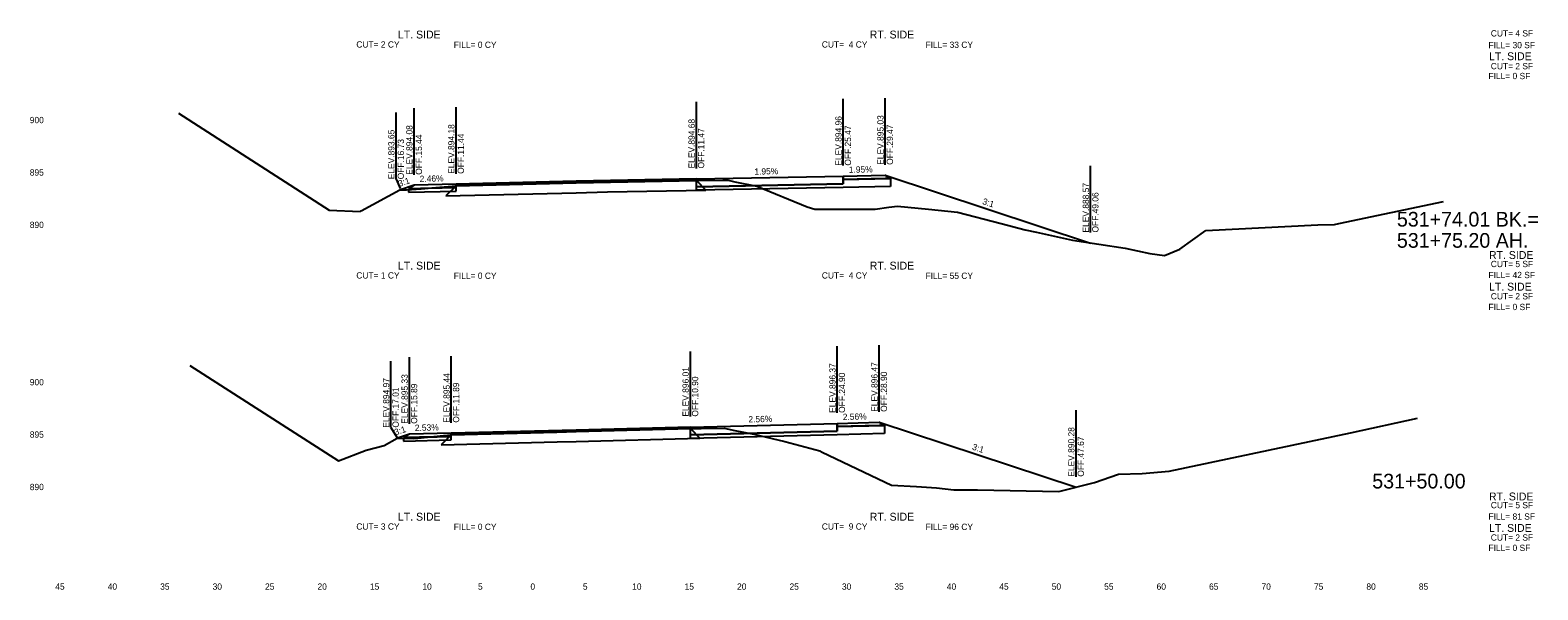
# Model space of a CAD drawing. Extents: x -4 to 359, y 0 to 1436.
# Drawn here: x -3.9 to 139.8, y 450.5 to 503.9 of the extents above; entities that cross this region are included whole.
import ezdxf

# ---------------------------------------------------------------- set-up
doc = ezdxf.new("R2010")
doc.units = 0
for name, color, linetype in [('XS-Existing subsurface-pavement', 7, 'Continuous'), ('XS-Existing surface-ground', 7, 'Continuous'), ('XS-Proposed Finish Grade', 7, 'Continuous'), ('XS-Proposed subsurface-aggregate layer 1', 7, 'Continuous'), ('XS-Proposed surface-ground', 7, 'Continuous'), ('XS-Proposed surface-pavement', 7, 'Continuous'), ('XS-Proposed surface-shoulder', 7, 'Continuous'), ('XS-Text-ditch slope', 7, 'Continuous'), ('XS-Text-earthwork labels', 7, 'Continuous'), ('XS-Text-elevation', 7, 'Continuous'), ('XS-Text-offset label', 7, 'Continuous'), ('XS-Text-pavement elevation', 7, 'Continuous'), ('XS-Text-pavement slope', 7, 'Continuous'), ('XS-Text-profile report', 7, 'Continuous'), ('XS-Text-shoulder elevation', 7, 'Continuous'), ('XS-Text-shoulder slope', 7, 'Continuous'), ('XS-Text-tie elevation', 7, 'Continuous'), ('XS-Text-tie offset', 7, 'Continuous')]:
    doc.layers.add(name, color=color, linetype=linetype)

msp = doc.modelspace()

# ---------------------------------------------------------------- linework, layer by layer
at = {"layer": 'XS-Existing subsurface-pavement'}
for p, q in [((36.69, 489.02), (35.73, 488.06)), ((59.6, 489.52), (60.52, 488.6)), ((35.73, 488.06), (48.15, 488.36)), ((48.15, 488.36), (51.14, 488.44)), ((51.13, 488.44), (60.52, 488.6)), ((59.03, 465.86), (59.94, 464.94)), ((36.24, 465.28), (35.27, 464.31)), ((35.27, 464.31), (46.32, 464.59)), ((46.32, 464.59), (48.15, 464.64)), ((48.15, 464.64), (59.94, 464.94))]:
    msp.add_line(p, q, dxfattribs=at)
at = {"layer": 'XS-Existing surface-ground'}
for p, q in [((10.24, 495.93), (24.58, 486.69)), ((33.37, 488.72), (34.39, 488.82)), ((34.39, 488.82), (36.69, 489.02)), ((36.69, 489.02), (48.13, 489.3)), ((48.13, 489.3), (51.11, 489.37)), ((51.11, 489.37), (59.6, 489.52)), ((59.6, 489.52), (62.12, 489.55)), ((62.12, 489.55), (62.62, 489.54)), ((62.62, 489.54), (63.26, 489.39)), ((63.26, 489.39), (65.38, 488.98)), ((65.38, 488.98), (70.18, 487.02)), ((27.66, 486.62), (31.33, 488.64)), ((31.33, 488.64), (31.96, 488.63)), ((31.96, 488.63), (33.37, 488.72)), ((120.87, 485.42), (130.82, 487.53)), ((24.58, 486.69), (27.55, 486.56)), ((27.55, 486.56), (27.66, 486.62)), ((70.18, 487.02), (70.91, 486.79)), ((70.91, 486.79), (71.91, 486.79)), ((71.91, 486.79), (76.65, 486.8)), ((76.65, 486.8), (77.95, 486.99)), ((77.95, 486.99), (78.77, 487.08)), ((78.77, 487.08), (81.73, 486.79)), ((81.73, 486.79), (84.49, 486.51)), ((84.49, 486.51), (88.65, 485.42)), ((88.65, 485.42), (90.96, 484.83)), ((90.96, 484.83), (92.04, 484.6)), ((92.04, 484.6), (95.47, 483.82)), ((105.69, 482.98), (108.19, 484.77)), ((108.19, 484.77), (118.86, 485.31)), ((118.86, 485.31), (120.43, 485.34)), ((120.43, 485.34), (120.87, 485.42)), ((95.47, 483.82), (100.48, 483.06)), ((100.48, 483.06), (102.83, 482.56)), ((104.24, 482.38), (105.69, 482.98)), ((102.83, 482.56), (104.24, 482.38)), ((11.32, 471.88), (25.5, 462.8)), ((48.13, 465.58), (59.03, 465.86)), ((59.03, 465.86), (60.07, 465.88)), ((60.07, 465.88), (62.24, 465.9)), ((62.24, 465.9), (63.26, 465.68)), ((121.98, 465.47), (128.34, 466.84)), ((29.83, 464.26), (31.08, 464.95)), ((31.08, 464.95), (32.59, 464.93)), ((32.59, 464.93), (33.05, 464.96)), ((33.05, 464.96), (35.5, 465.21)), ((35.5, 465.21), (36.24, 465.28)), ((36.24, 465.28), (46.3, 465.53)), ((46.3, 465.53), (48.13, 465.58)), ((63.26, 465.68), (65.07, 465.33)), ((65.07, 465.33), (68.05, 464.63)), ((68.05, 464.63), (71.36, 463.73)), ((104.68, 461.79), (121.98, 465.47)), ((25.5, 462.8), (28.11, 463.8)), ((28.11, 463.8), (29.83, 464.26)), ((71.36, 463.73), (71.59, 463.6)), ((71.59, 463.6), (78.21, 460.45)), ((97.56, 460.72), (99.85, 461.51)), ((99.85, 461.51), (102.09, 461.57)), ((102.09, 461.57), (104.68, 461.79)), ((78.21, 460.45), (80.58, 460.33)), ((80.58, 460.33), (82.5, 460.21)), ((82.5, 460.21), (84.16, 460.02)), ((84.16, 460.02), (86.41, 460.01)), ((86.41, 460.01), (94.16, 459.85)), ((94.16, 459.85), (97.56, 460.72))]:
    msp.add_line(p, q, dxfattribs=at)
at = {"layer": 'XS-Proposed Finish Grade'}
for points in [[(36.69, 489.16), (32.69, 489.07)], [(36.69, 489.16), (48.13, 489.45), (59.6, 489.67)], [(59.6, 489.67), (73.6, 489.94)], [(73.6, 489.94), (77.6, 490.02)], [(36.24, 465.42), (48.13, 465.72), (59.03, 466)], [(59.03, 466), (73.03, 466.36)], [(73.03, 466.36), (77.03, 466.46)], [(36.24, 465.42), (32.24, 465.32)]]:
    msp.add_lwpolyline(points, dxfattribs=at)
at = {"layer": 'XS-Proposed subsurface-aggregate layer 1'}
for points in [[(36.69, 488.85), (32.15, 488.74)], [(32.15, 488.74), (32.15, 488.41)], [(36.69, 488.52), (36.69, 488.85)], [(59.6, 488.92), (73.6, 489.19)], [(78.1, 488.95), (73.6, 488.86), (59.6, 488.59)], [(59.6, 488.59), (59.6, 488.92)], [(73.6, 489.63), (78.1, 489.72)], [(73.6, 489.19), (73.6, 489.63)], [(78.1, 489.72), (78.1, 488.95)], [(32.15, 488.41), (36.69, 488.52)], [(73.03, 466.05), (77.53, 466.16)], [(73.03, 465.61), (73.03, 466.05)], [(77.53, 466.16), (77.53, 465.39)], [(36.24, 465.11), (31.69, 465)], [(31.69, 465), (31.69, 464.66)], [(31.69, 464.66), (36.24, 464.78)], [(36.24, 464.78), (36.24, 465.11)], [(59.03, 465.25), (73.03, 465.61)], [(77.53, 465.39), (73.03, 465.28), (59.03, 464.92)], [(59.03, 464.92), (59.03, 465.25)]]:
    msp.add_lwpolyline(points, dxfattribs=at)
at = {"layer": 'XS-Proposed surface-ground'}
for points in [[(32.69, 489.07), (31.4, 488.64)], [(77.6, 490.02), (97.19, 483.56)], [(77.03, 466.46), (95.8, 460.27)], [(32.24, 465.32), (31.12, 464.95)]]:
    msp.add_lwpolyline(points, dxfattribs=at)
at = {"layer": 'XS-Proposed surface-pavement'}
for points in [[(59.6, 489.67), (48.13, 489.45), (36.69, 489.16)], [(36.69, 489.02), (48.13, 489.3), (59.6, 489.52)], [(36.69, 489.16), (36.69, 489.02)], [(59.6, 489.67), (73.6, 489.94)], [(59.6, 488.92), (59.6, 489.67)], [(59.6, 489.52), (59.6, 489.67)], [(73.6, 489.19), (59.6, 488.92)], [(73.6, 489.94), (73.6, 489.19)], [(59.03, 466), (48.13, 465.72), (36.24, 465.42)], [(36.24, 465.28), (48.13, 465.58), (59.03, 465.86)], [(59.03, 466), (73.03, 466.36)], [(59.03, 465.25), (59.03, 466)], [(59.03, 465.86), (59.03, 466)], [(73.03, 466.36), (73.03, 465.61)], [(36.24, 465.42), (36.24, 465.28)], [(73.03, 465.61), (59.03, 465.25)]]:
    msp.add_lwpolyline(points, dxfattribs=at)
at = {"layer": 'XS-Proposed surface-shoulder'}
for points in [[(36.69, 489.16), (32.69, 489.07), (32.15, 488.74)], [(32.15, 488.74), (32.69, 488.75), (36.69, 488.85)], [(36.69, 488.85), (36.69, 489.16)], [(73.6, 489.94), (77.6, 490.02), (78.1, 489.72)], [(73.6, 489.63), (73.6, 489.94)], [(78.1, 489.72), (77.6, 489.71), (73.6, 489.63)], [(73.03, 466.36), (77.03, 466.46), (77.53, 466.16)], [(73.03, 466.05), (73.03, 466.36)], [(77.53, 466.16), (77.03, 466.15), (73.03, 466.05)], [(36.24, 465.42), (32.24, 465.32), (31.69, 465)], [(31.69, 465), (32.24, 465.01), (36.24, 465.11)], [(36.24, 465.11), (36.24, 465.42)]]:
    msp.add_lwpolyline(points, dxfattribs=at)
at = {"layer": 'XS-Text-tie offset'}
for p, q in [((77.6, 491.02), (77.6, 497.37)), ((30.97, 489.64), (30.97, 496)), ((32.69, 490.07), (32.69, 496.42)), ((36.69, 490.16), (36.69, 496.51)), ((59.6, 490.67), (59.6, 497.02)), ((73.6, 490.94), (73.6, 497.32)), ((97.19, 484.56), (97.19, 490.91)), ((30.97, 489.64), (31.35, 488.75)), ((59.03, 467), (59.03, 473.2)), ((73.03, 467.36), (73.03, 473.71)), ((77.03, 467.46), (77.03, 473.81)), ((30.48, 465.95), (30.48, 472.3)), ((32.24, 466.32), (32.24, 472.67)), ((36.24, 466.42), (36.24, 472.77)), ((95.8, 461.27), (95.8, 467.62)), ((30.48, 465.95), (31.06, 465.03))]:
    msp.add_line(p, q, dxfattribs=at)

# ---------------------------------------------------------------- texts
at = {"layer": 'XS-Text-ditch slope'}
for rotation, p in [(18.2629, (31.29, 488.92)), (341.7371, (86.82, 487.29)), (18.2629, (30.92, 465.2)), (341.7371, (85.85, 463.87))]:
    msp.add_text('3:1', height=0.6, rotation=rotation, dxfattribs=at).set_placement(p)
at = {"layer": 'XS-Text-earthwork labels'}
for s, height, p in [('LT. SIDE', 0.75, (31.15, 503.07)), ('RT. SIDE', 0.75, (76.13, 503.07)), (' CUT= 4 SF           ', 0.6, (135.12, 503.26)), (' CUT= 2 CY           ', 0.6, (26.96, 502.2)), ('FILL= 0 CY           ', 0.6, (36.47, 502.17)), (' CUT=  4 CY           ', 0.6, (71.34, 502.2)), ('FILL= 33 CY           ', 0.6, (81.45, 502.17)), ('FILL= 30 SF           ', 0.6, (135.12, 502.14)), ('LT. SIDE', 0.75, (135.17, 501)), (' CUT= 2 SF           ', 0.6, (135.12, 500.13)), ('FILL= 0 SF           ', 0.6, (135.12, 499.19)), ('LT. SIDE', 0.75, (31.15, 481.03)), ('RT. SIDE', 0.75, (76.13, 481.03)), ('RT. SIDE', 0.75, (135.17, 482.04)), (' CUT= 5 SF           ', 0.6, (135.12, 481.26)), (' CUT= 1 CY           ', 0.6, (26.96, 480.17)), ('FILL= 0 CY           ', 0.6, (36.47, 480.14)), (' CUT=  4 CY           ', 0.6, (71.34, 480.17)), ('FILL= 55 CY           ', 0.6, (81.45, 480.14)), ('FILL= 42 SF           ', 0.6, (135.12, 480.21)), ('LT. SIDE', 0.75, (135.17, 479.02)), (' CUT= 2 SF           ', 0.6, (135.12, 478.18)), ('FILL= 0 SF           ', 0.6, (135.12, 477.16)), ('RT. SIDE', 0.75, (135.17, 459.01)), (' CUT= 5 SF           ', 0.6, (135.12, 458.26)), ('LT. SIDE', 0.75, (31.15, 457.08)), ('RT. SIDE', 0.75, (76.13, 457.08)), ('FILL= 81 SF           ', 0.6, (135.12, 457.17)), (' CUT= 3 CY           ', 0.6, (26.96, 456.22)), ('FILL= 0 CY           ', 0.6, (36.47, 456.19)), (' CUT=  9 CY           ', 0.6, (71.34, 456.22)), ('FILL= 96 CY           ', 0.6, (81.45, 456.19)), ('LT. SIDE', 0.75, (135.17, 456.01)), (' CUT= 2 SF           ', 0.6, (135.12, 455.17)), ('FILL= 0 SF           ', 0.6, (135.12, 454.18))]:
    msp.add_text(s, height=height, dxfattribs=at).set_placement(p)
at = {"layer": 'XS-Text-elevation'}
for s, p in [('           900           ', (-6.4, 494.99)), ('           895           ', (-6.4, 489.99)), ('           890           ', (-6.4, 484.99)), ('           900           ', (-6.4, 469.99)), ('           895           ', (-6.4, 464.99)), ('           890           ', (-6.4, 459.99))]:
    msp.add_text(s, height=0.6, dxfattribs=at).set_placement(p)
at = {"layer": 'XS-Text-offset label'}
for s, height, p in [('531+74.01 BK.= ', 1.4, (126.39, 485.13)), ('531+75.20 AH.          ', 1.4, (126.39, 483.11)), ('           531+50.00           ', 1.4, (118.32, 460.15)), ('           45           ', 0.6, (-3.97, 450.49)), ('           40           ', 0.6, (1.03, 450.49)), ('           35           ', 0.6, (6.03, 450.49)), ('           30           ', 0.6, (11.03, 450.49)), ('           25           ', 0.6, (16.03, 450.49)), ('           20           ', 0.6, (21.03, 450.49)), ('           15           ', 0.6, (26.03, 450.49)), ('           10           ', 0.6, (31.03, 450.49)), ('           5           ', 0.6, (36.33, 450.49)), ('           0           ', 0.6, (41.33, 450.49)), ('           0           ', 0.6, (41.33, 450.49)), ('           5           ', 0.6, (46.33, 450.49)), ('           10           ', 0.6, (51.03, 450.49)), ('           15           ', 0.6, (56.03, 450.49)), ('           20           ', 0.6, (61.03, 450.49)), ('           25           ', 0.6, (66.03, 450.49)), ('           30           ', 0.6, (71.03, 450.49)), ('           35           ', 0.6, (76.03, 450.49)), ('           40           ', 0.6, (81.03, 450.49)), ('           45           ', 0.6, (86.03, 450.49)), ('           50           ', 0.6, (91.03, 450.49)), ('           55           ', 0.6, (96.03, 450.49)), ('           60           ', 0.6, (101.03, 450.49)), ('           65           ', 0.6, (106.03, 450.49)), ('           70           ', 0.6, (111.03, 450.49)), ('           75           ', 0.6, (116.03, 450.49)), ('           80           ', 0.6, (121.03, 450.49)), ('           85           ', 0.6, (126.03, 450.49))]:
    msp.add_text(s, height=height, dxfattribs=at).set_placement(p)
at = {"layer": 'XS-Text-pavement elevation'}
for s, p in [('ELEV.894.08', (32.54, 490.07)), ('ELEV.894.18', (36.54, 490.16)), ('ELEV.894.68', (59.45, 490.67)), ('ELEV.894.96', (73.45, 490.94)), ('OFF.25.47', (74.35, 490.94)), ('OFF.15.44', (33.44, 490.07)), ('OFF.11.44', (37.44, 490.16)), ('OFF.11.47', (60.35, 490.67)), ('ELEV.896.01', (58.88, 467)), ('ELEV.896.37', (72.88, 467.36)), ('ELEV.895.33', (32.09, 466.32)), ('OFF.15.89', (32.99, 466.32)), ('ELEV.895.44', (36.09, 466.42)), ('OFF.11.89', (36.99, 466.42)), ('OFF.10.90', (59.78, 467)), ('OFF.24.90', (73.78, 467.36))]:
    msp.add_text(s, height=0.6, rotation=90, dxfattribs=at).set_placement(p)
at = {"layer": 'XS-Text-pavement slope'}
for s, rotation, p in [('1.95%', 1.1189, (65.14, 490.08)), ('2.56%', 1.4638, (64.57, 466.44))]:
    msp.add_text(s, height=0.6, rotation=rotation, dxfattribs=at).set_placement(p)
at = {"layer": 'XS-Text-profile report'}
for s, p in [('Shldr_Surf_Asph_B2', (32.13, 488.74)), ('Shldr_Surf_Asph_T1', (32.68, 489.06)), ('Shldr_Surf_Asph_B1', (32.68, 488.75)), ('Pvmt_Surf_Asph_T2_L', (36.68, 489.16)), ('Pvmt_Surf_Asph_T_L', (36.68, 489.02)), ('Shldr_Surf_Asph_B12', (36.68, 488.85)), ('Pvmt_Surf_Asph_T1', (48.12, 489.44)), ('Pvmt_Surf_Asph_T', (48.12, 489.3)), ('Pvmt_Surf_Asph_T1_R', (59.58, 489.67)), ('Pvmt_Surf_Asph_T_R', (59.58, 489.52)), ('Pvmt_Surf_Conc_B_R', (59.58, 488.92)), ('Shldr_Surf_Asph_B111', (73.58, 489.63)), ('Pvmt_Surf_Conc_T1_R', (73.59, 489.94)), ('Pvmt_Surf_Conc_B1_R', (73.59, 489.19)), ('Agg_Layer_1_B11', (73.59, 488.86)), ('Shldr_Surf_Asph_T11', (77.59, 490.02)), ('Shldr_Surf_Asph_B11', (77.59, 489.71)), ('Shldr_Surf_Asph_B21', (78.09, 489.72)), ('Agg_Layer_1_B12', (78.09, 488.95)), ('Rt_Agg_Layer_1_B13', (80.69, 489)), ('Fill_Slope_2_B', (31.39, 488.64)), ('Agg_Layer_1_B1', (32.14, 488.41)), ('Agg_Layer_1_B', (36.68, 488.52)), ('Agg_Layer_1_B2', (59.58, 488.59)), ('Fill_Slope_2_B1', (97.18, 483.56)), ('Pvmt_Surf_Asph_T1', (48.12, 465.72)), ('Pvmt_Surf_Asph_T1_R', (59.01, 466)), ('Pvmt_Surf_Asph_T_R', (59.01, 465.85)), ('Pvmt_Surf_Conc_T1_R', (73.02, 466.36)), ('Shldr_Surf_Asph_B111', (73.02, 466.05)), ('Shldr_Surf_Asph_T11', (77.02, 466.46)), ('Shldr_Surf_Asph_B11', (77.02, 466.15)), ('Shldr_Surf_Asph_B21', (77.52, 466.16)), ('Fill_Slope_2_B', (31.11, 464.95)), ('Shldr_Surf_Asph_B2', (31.68, 464.99)), ('Agg_Layer_1_B1', (31.68, 464.66)), ('Shldr_Surf_Asph_T1', (32.22, 465.32)), ('Shldr_Surf_Asph_B1', (32.22, 465.01)), ('Pvmt_Surf_Asph_T2_L', (36.22, 465.42)), ('Pvmt_Surf_Asph_T_L', (36.22, 465.28)), ('Shldr_Surf_Asph_B12', (36.22, 465.11)), ('Agg_Layer_1_B', (36.23, 464.78)), ('Pvmt_Surf_Asph_T', (48.12, 465.58)), ('Pvmt_Surf_Conc_B_R', (59.01, 465.25)), ('Agg_Layer_1_B2', (59.02, 464.92)), ('Pvmt_Surf_Conc_B1_R', (73.02, 465.61)), ('Agg_Layer_1_B11', (73.02, 465.28)), ('Agg_Layer_1_B12', (77.52, 465.39)), ('Rt_Agg_Layer_1_B13', (80.06, 465.46)), ('Fill_Slope_2_B1', (95.79, 460.27))]:
    msp.add_text(s, height=0.00167, dxfattribs=at).set_placement(p)
at = {"layer": 'XS-Text-shoulder elevation'}
for s, p in [('ELEV.895.03', (77.45, 491.02)), ('OFF.29.47', (78.35, 491.02)), ('ELEV.896.47', (76.88, 467.46)), ('OFF.28.90', (77.78, 467.46))]:
    msp.add_text(s, height=0.6, rotation=90, dxfattribs=at).set_placement(p)
at = {"layer": 'XS-Text-shoulder slope'}
for s, rotation, p in [('1.95%', 1.1189, (74.14, 490.25)), ('2.46%', 1.4104, (33.23, 489.38)), ('2.56%', 1.4638, (73.57, 466.67)), ('2.53%', 1.4475, (32.77, 465.63))]:
    msp.add_text(s, height=0.6, rotation=rotation, dxfattribs=at).set_placement(p)
at = {"layer": 'XS-Text-tie elevation'}
for s, p in [('ELEV.893.65', (30.82, 489.64)), ('OFF.16.73', (31.72, 489.64)), ('ELEV.888.57', (97.04, 484.56)), ('OFF.49.06', (97.94, 484.56)), ('ELEV.894.97', (30.33, 465.95)), ('OFF.17.01', (31.23, 465.95)), ('ELEV.890.28', (95.65, 461.27)), ('OFF.47.67', (96.55, 461.27))]:
    msp.add_text(s, height=0.6, rotation=90, dxfattribs=at).set_placement(p)

doc.saveas('drawing.dxf')
